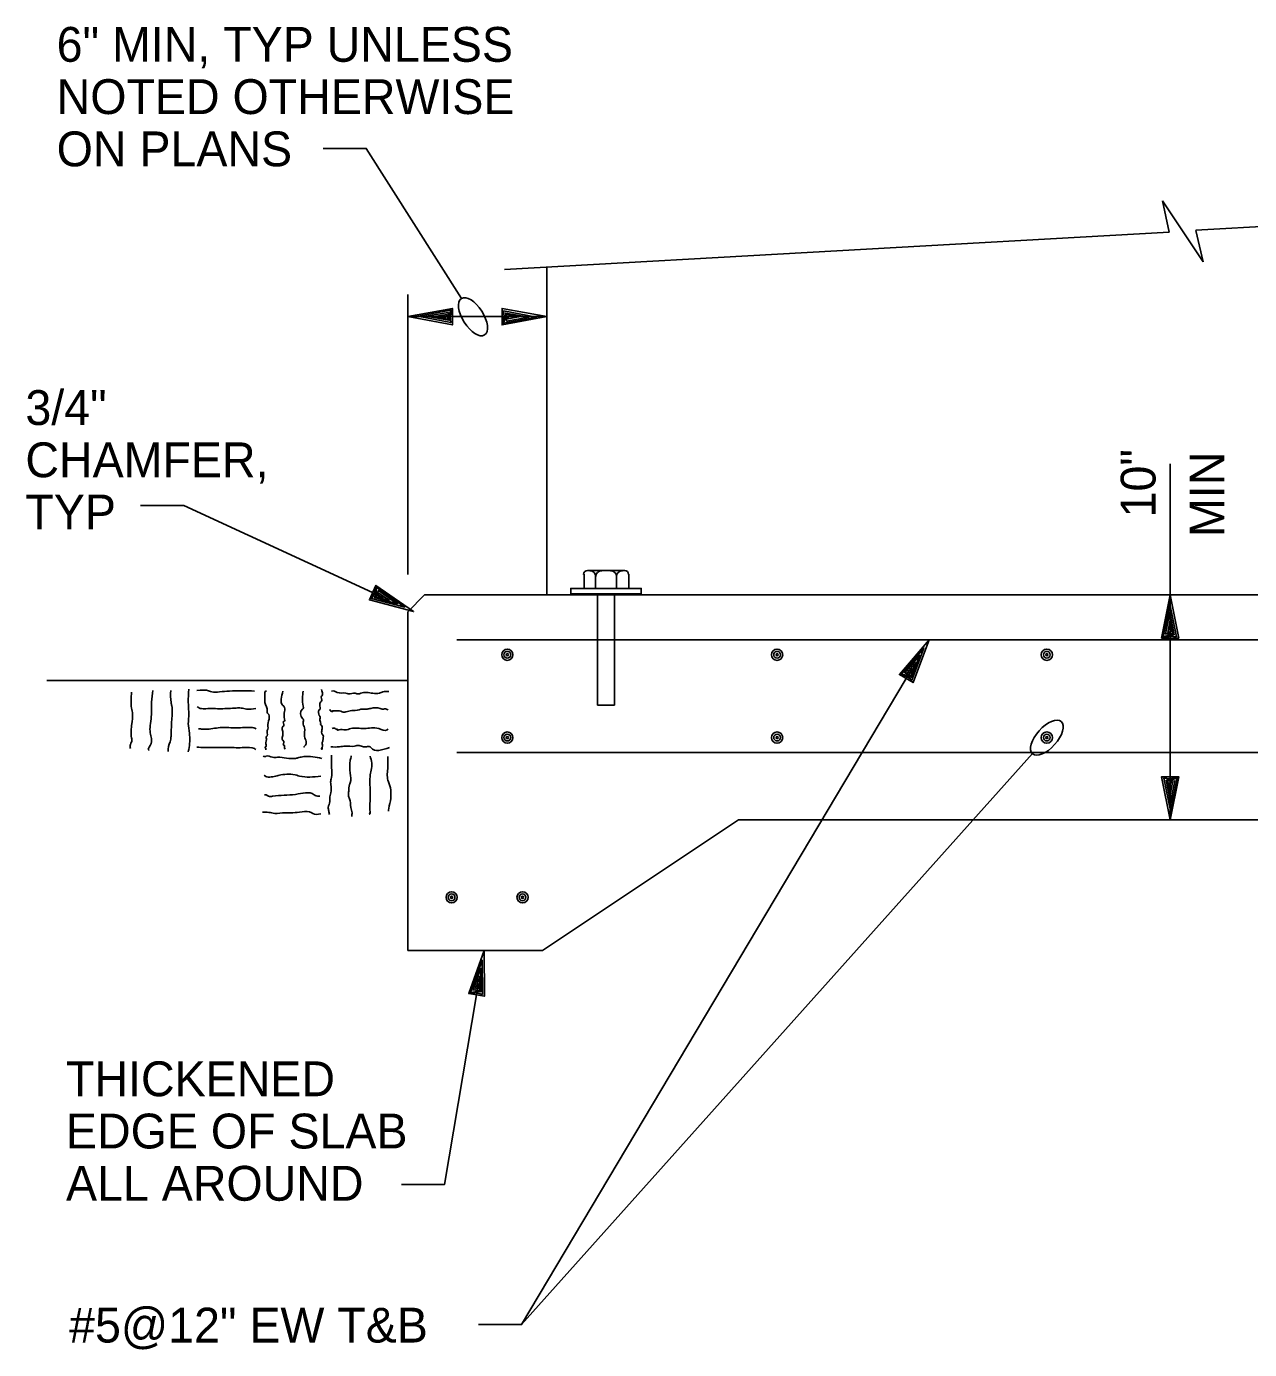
# Model space of a CAD drawing. Extents: x -121875 to -117742, y -103854 to -101122.
# Drawn here: x -121845.8 to -121635, y -102442.1 to -102214.2 of the extents above; entities that cross this region are included whole.
import ezdxf

# ---------------------------------------------------------------- set-up
doc = ezdxf.new("R2010")
doc.units = 0
for name, color, linetype in [('G-MARK', 7, 'Continuous'), ('G-TEXT', 7, 'Continuous'), ('Misc CnstDet(22)', 7, 'Continuous')]:
    doc.layers.add(name, color=color, linetype=linetype)

msp = doc.modelspace()

# ---------------------------------------------------------------- linework, layer by layer
at = {"layer": 'G-MARK'}
for p, q in [((-121756.12, -102255.67), (-121756.12, -102312.1)), ((-121780.06, -102308.56), (-121780.06, -102260.32)), ((-121780.06, -102264.16), (-121756.12, -102264.16)), ((-121648.67, -102289.5), (-121648.67, -102312.1)), ((-121648.67, -102312.1), (-121648.67, -102350.84))]:
    msp.add_line(p, q, dxfattribs=at)
for points in [[(-121794.66, -102235.19), (-121787.21, -102235.19), (-121770.8, -102261.05)], [(-121826.11, -102296.67), (-121818.67, -102296.67), (-121786.12, -102311.7)], [(-121767.88, -102437.78), (-121760.44, -102437.78), (-121694.16, -102326.51)], [(-121767.88, -102437.78), (-121760.44, -102437.78), (-121672.39, -102339.42)], [(-121781.17, -102413.63), (-121773.73, -102413.63), (-121768.21, -102380.99)]]:
    msp.add_lwpolyline(points, dxfattribs=at)
at = {"layer": 'G-TEXT'}
for points in [[(-121772.37, -102262.74), (-121772.37, -102265.59), (-121780.06, -102264.16), (-121772.37, -102262.74), (-121772.74, -102264.16), (-121772.62, -102265.16), (-121778.32, -102264.1), (-121772.62, -102263.05), (-121772.99, -102264.16), (-121772.99, -102264.78), (-121776.96, -102264.1), (-121773.12, -102263.42), (-121773.18, -102264.6), (-121775.53, -102264.16), (-121773.36, -102263.79), (-121773.55, -102264.35), (-121774.29, -102264.16), (-121772.37, -102264.16)], [(-121763.81, -102265.59), (-121763.81, -102262.74), (-121756.12, -102264.16), (-121763.81, -102265.59), (-121763.44, -102264.16), (-121763.56, -102263.17), (-121757.86, -102264.23), (-121763.56, -102265.28), (-121763.19, -102264.16), (-121763.19, -102263.54), (-121759.22, -102264.23), (-121763.07, -102264.91), (-121763.01, -102263.73), (-121760.65, -102264.16), (-121762.82, -102264.54), (-121762.63, -102263.98), (-121761.89, -102264.16), (-121763.81, -102264.16)], [(-121785.55, -102310.46), (-121786.69, -102312.94), (-121779.08, -102314.95), (-121785.55, -102310.46), (-121785.78, -102311.86), (-121786.31, -102312.71), (-121780.58, -102314.2), (-121785.43, -102310.79), (-121785.56, -102311.96), (-121785.81, -102312.53), (-121781.87, -102313.6), (-121785.13, -102311.34), (-121785.57, -102312.44), (-121783.19, -102313.06), (-121785.06, -102311.78), (-121785.13, -102312.37), (-121784.32, -102312.54), (-121786.12, -102311.71)], [(-121650.16, -102319.54), (-121647.19, -102319.54), (-121648.67, -102312.1), (-121650.16, -102319.54), (-121648.67, -102319.18), (-121647.59, -102319.3), (-121648.74, -102313.71), (-121649.89, -102319.3), (-121648.67, -102318.94), (-121648, -102318.94), (-121648.74, -102315.07), (-121649.49, -102318.82), (-121648.2, -102318.77), (-121648.67, -102316.44), (-121649.08, -102318.59), (-121648.47, -102318.41), (-121648.67, -102317.63), (-121648.67, -102319.54)], [(-121695.33, -102325.81), (-121692.98, -102327.2), (-121690.19, -102319.85), (-121695.33, -102325.81), (-121693.96, -102326.19), (-121693.18, -102326.8), (-121691.1, -102321.25), (-121694.99, -102325.72), (-121693.84, -102325.97), (-121693.3, -102326.29), (-121691.83, -102322.48), (-121694.41, -102325.49), (-121693.37, -102326.04), (-121692.5, -102323.74), (-121693.97, -102325.46), (-121693.39, -102325.59), (-121693.14, -102324.8), (-121694.15, -102326.51)], [(-121647.19, -102343.4), (-121650.16, -102343.4), (-121648.67, -102350.84), (-121647.19, -102343.4), (-121648.67, -102343.76), (-121649.76, -102343.64), (-121648.61, -102349.23), (-121647.46, -102343.64), (-121648.67, -102344), (-121649.35, -102344), (-121648.61, -102347.86), (-121647.86, -102344.11), (-121649.15, -102344.17), (-121648.67, -102346.5), (-121648.27, -102344.35), (-121648.88, -102344.53), (-121648.67, -102345.31), (-121648.67, -102343.4)], [(-121769.55, -102380.76), (-121766.86, -102381.22), (-121766.91, -102373.35), (-121769.55, -102380.76), (-121768.14, -102380.62), (-121767.19, -102380.91), (-121767.25, -102374.99), (-121769.27, -102380.56), (-121768.1, -102380.38), (-121767.49, -102380.48), (-121767.49, -102376.39), (-121768.82, -102380.13), (-121767.64, -102380.27), (-121767.67, -102377.81), (-121768.41, -102379.95), (-121767.83, -102379.86), (-121767.88, -102379.03), (-121768.21, -102380.99)]]:
    msp.add_lwpolyline(points, dxfattribs=at)
for centre, major_axis in [((-121768.83, -102264.17), (1.99, -3.14)), ((-121669.92, -102336.68), (2.48, 2.77))]:
    msp.add_ellipse(centre, major_axis=major_axis, ratio=0.483333, dxfattribs=at)
at = {"layer": 'Misc CnstDet(22)'}
for p, q in [((-121644.26, -102249.28), (-121531.59, -102242.89)), ((-121648.85, -102249.59), (-121649.97, -102244.2)), ((-121642.96, -102254.74), (-121649.97, -102244.2)), ((-121763.38, -102256.04), (-121648.85, -102249.59)), ((-121648.85, -102249.59), (-121648.85, -102249.59)), ((-121642.96, -102254.74), (-121644.26, -102249.34)), ((-121644.26, -102249.34), (-121644.26, -102249.34)), ((-121756.12, -102264.16), (-121756.12, -102264.16)), ((-121749.68, -102310.98), (-121749.68, -102308.5)), ((-121749.06, -102307.88), (-121742.73, -102307.88)), ((-121747.69, -102310.98), (-121747.69, -102308.87)), ((-121744.1, -102310.98), (-121744.1, -102308.87)), ((-121741.99, -102310.98), (-121741.99, -102308.5)), ((-121780.06, -102315), (-121777.16, -102312.1)), ((-121777.16, -102312.1), (-121516.95, -102312.1)), ((-121747.35, -102311.91), (-121747.35, -102331.1)), ((-121744.44, -102311.91), (-121744.44, -102331.1)), ((-121641.32, -102312.1), (-121652.39, -102312.1)), ((-121780.06, -102315), (-121780.06, -102373.35)), ((-121771.63, -102319.85), (-121522.48, -102319.85)), ((-121780.06, -102326.86), (-121842.26, -102326.86)), ((-121747.35, -102331.1), (-121744.44, -102331.1)), ((-121771.63, -102339.22), (-121522.48, -102339.22)), ((-121756.82, -102373.35), (-121723.06, -102350.84)), ((-121723.06, -102350.84), (-121571.05, -102350.84)), ((-121642.71, -102350.84), (-121652.39, -102350.84)), ((-121780.06, -102373.35), (-121756.81, -102373.35))]:
    msp.add_line(p, q, dxfattribs=at)
msp.add_lwpolyline([(-121751.97, -102311.91), (-121739.82, -102311.91), (-121739.82, -102310.98), (-121751.97, -102310.98)], close=True, dxfattribs=at)
for centre, radius in [((-121762.91, -102322.39), 0.969), ((-121716.42, -102322.39), 0.969), ((-121669.93, -102322.39), 0.969), ((-121762.91, -102322.39), 0.581), ((-121762.91, -102322.39), 0.176), ((-121716.42, -102322.39), 0.581), ((-121716.42, -102322.39), 0.176), ((-121669.93, -102322.39), 0.581), ((-121669.93, -102322.39), 0.176), ((-121762.91, -102336.67), 0.969), ((-121762.91, -102336.67), 0.581), ((-121762.91, -102336.67), 0.176), ((-121716.42, -102336.67), 0.969), ((-121716.42, -102336.67), 0.581), ((-121716.42, -102336.67), 0.176), ((-121669.93, -102336.67), 0.969), ((-121669.93, -102336.67), 0.581), ((-121669.93, -102336.67), 0.176), ((-121772.51, -102364.18), 0.969), ((-121772.51, -102364.18), 0.581), ((-121772.51, -102364.18), 0.176), ((-121760.29, -102364.18), 0.969), ((-121760.29, -102364.18), 0.581), ((-121760.29, -102364.18), 0.176)]:
    msp.add_circle(centre, radius, dxfattribs=at)
for centre, radius, start, end in [((-121749.08, -102308.56), 0.674, 90, 180), ((-121748.68, -102308.93), 1.01, 360, 90), ((-121746.65, -102308.93), 1.01, 90, 180), ((-121745.1, -102308.93), 1.01, 360, 90), ((-121743.08, -102308.93), 1.01, 90, 180), ((-121742.68, -102308.56), 0.674, 0, 90)]:
    msp.add_arc(centre, radius, start, end, dxfattribs=at)
for points in [[(-121817.82, -102328.34), (-121817.89, -102330.64), (-121817.82, -102333.06), (-121817.89, -102334.23), (-121817.7, -102335.91), (-121817.64, -102337.33), (-121817.82, -102338.7), (-121817.89, -102339.13)], [(-121827.68, -102328.84), (-121827.68, -102331.57), (-121827.5, -102332.62), (-121827.62, -102334.3), (-121827.68, -102336.71), (-121827.68, -102337.46), (-121827.87, -102337.83), (-121827.87, -102338.57)], [(-121824.02, -102328.53), (-121824.21, -102330.58), (-121824.27, -102333.06), (-121824.46, -102334.61), (-121824.46, -102335.85), (-121824.46, -102338.02), (-121824.71, -102338.82), (-121824.64, -102338.82)], [(-121820.92, -102328.53), (-121820.86, -102330.64), (-121820.74, -102331.2), (-121820.74, -102333.61), (-121820.86, -102336.28), (-121820.92, -102336.96), (-121821.36, -102338.64), (-121821.36, -102339.07)], [(-121806.48, -102328.65), (-121810.82, -102328.65), (-121812.49, -102328.78), (-121813.86, -102328.78), (-121814.23, -102328.65), (-121816.4, -102328.53)], [(-121804.43, -102328.65), (-121804.55, -102328.65), (-121804.68, -102329.4), (-121804.68, -102330.64), (-121804.31, -102332.13), (-121804.31, -102332.37), (-121804.18, -102332.5), (-121804.18, -102334.73), (-121804.18, -102335.23), (-121804.31, -102335.47), (-121804.31, -102336.34), (-121804.43, -102336.47), (-121804.43, -102337.02), (-121804.55, -102337.52), (-121804.55, -102338.26), (-121804.68, -102338.39), (-121804.55, -102338.51), (-121804.55, -102338.76)], [(-121801.58, -102328.65), (-121801.58, -102331.13), (-121801.45, -102331.26), (-121801.33, -102333.49), (-121801.33, -102333.86), (-121801.45, -102333.86), (-121801.45, -102334.61), (-121801.58, -102334.73), (-121801.58, -102335.97), (-121801.58, -102337.15), (-121801.45, -102337.27), (-121801.45, -102338.02), (-121801.33, -102338.02), (-121801.33, -102338.26), (-121801.2, -102338.64)], [(-121798.1, -102328.65), (-121798.1, -102331.26), (-121798.1, -102331.63), (-121798.23, -102331.75), (-121798.23, -102333.37), (-121798.1, -102333.49), (-121798.1, -102334.11), (-121797.86, -102334.98), (-121797.86, -102336.47), (-121797.86, -102338.14), (-121797.98, -102338.26), (-121797.86, -102338.26)], [(-121794.94, -102328.41), (-121794.82, -102328.78), (-121794.82, -102329.4), (-121794.94, -102329.52), (-121794.94, -102330.39), (-121795.07, -102330.51), (-121795.19, -102331.51), (-121795.19, -102331.75), (-121795.31, -102331.88), (-121795.31, -102332.87), (-121795.19, -102333.12), (-121795.19, -102333.86), (-121795.07, -102334.11), (-121795.07, -102334.48), (-121794.94, -102334.61), (-121794.82, -102336.09), (-121794.69, -102336.22), (-121794.69, -102337.15), (-121794.69, -102337.27), (-121794.82, -102337.52), (-121794.82, -102338.39), (-121794.94, -102338.64), (-121794.82, -102338.64), (-121794.82, -102338.51)], [(-121783.35, -102328.72), (-121784.34, -102328.78), (-121784.96, -102329.03), (-121786.08, -102329.03), (-121788.18, -102329.03), (-121788.56, -102329.15), (-121789.11, -102329.03), (-121790.35, -102329.15), (-121790.73, -102329.03), (-121792.21, -102328.9), (-121792.71, -102328.65), (-121793.21, -102328.65)], [(-121806.23, -102331.63), (-121807.84, -102331.75), (-121808.77, -102331.57), (-121809.64, -102331.57), (-121812.24, -102331.69), (-121814.85, -102331.69), (-121815.84, -102331.63), (-121816.34, -102331.38)], [(-121783.47, -102331.88), (-121783.72, -102331.75), (-121784.46, -102331.75), (-121784.84, -102331.63), (-121786.45, -102331.63), (-121787.07, -102331.75), (-121787.81, -102331.75), (-121789.11, -102332), (-121789.73, -102332), (-121790.73, -102332.25), (-121791.35, -102332.25), (-121791.59, -102332.13), (-121793.08, -102332.13), (-121792.96, -102332.13), (-121793.45, -102332), (-121793.45, -102331.88), (-121793.45, -102332)], [(-121806.17, -102335.16), (-121806.41, -102335.04), (-121807.28, -102334.92), (-121809.82, -102334.98), (-121812.74, -102334.98), (-121815.22, -102335.23), (-121815.96, -102335.16), (-121816.15, -102335.16)], [(-121783.47, -102335.23), (-121783.6, -102335.35), (-121785.08, -102335.1), (-121787.56, -102335.1), (-121789.86, -102335.1), (-121790.85, -102335.35), (-121791.97, -102335.35), (-121792.21, -102335.35), (-121792.21, -102335.23), (-121792.21, -102335.35), (-121792.21, -102335.23), (-121792.46, -102335.23), (-121792.59, -102335.1), (-121793.08, -102335.1)], [(-121806.23, -102338.7), (-121806.48, -102338.57), (-121808.27, -102338.39), (-121811, -102338.39), (-121813.79, -102338.39), (-121816.4, -102338.33)], [(-121794.88, -102340.25), (-121797.98, -102339.94), (-121798.85, -102340.12), (-121799.41, -102340.25), (-121802.51, -102340.06), (-121803.38, -102340.06), (-121804.49, -102339.88), (-121804.62, -102339.94), (-121804.99, -102339.88)], [(-121793.21, -102339.69), (-121793.21, -102341.86), (-121793.21, -102343.53), (-121793.33, -102343.97), (-121793.33, -102344.77), (-121793.33, -102346.2), (-121793.52, -102347.13), (-121793.52, -102347.69), (-121793.76, -102348.68), (-121793.7, -102349.3), (-121793.58, -102349.92)], [(-121783.22, -102338.39), (-121786.45, -102338.39), (-121786.57, -102338.26), (-121787.19, -102338.26), (-121787.69, -102338.26), (-121788.43, -102338.02), (-121789.24, -102338.14), (-121790.85, -102338.14), (-121791.84, -102338.26), (-121793.33, -102338.26)], [(-121789.8, -102339.81), (-121789.98, -102340.56), (-121789.98, -102342.79), (-121789.98, -102344.46), (-121790.11, -102344.77), (-121790.23, -102345.89), (-121790.29, -102346.64), (-121790.11, -102347.19), (-121789.86, -102348.68), (-121789.67, -102349.61), (-121789.73, -102350.23)], [(-121786.57, -102339.88), (-121786.26, -102341.05), (-121786.39, -102342.29), (-121786.57, -102343.35), (-121786.57, -102345.27), (-121786.57, -102347.57), (-121786.57, -102349.49), (-121786.57, -102349.74), (-121786.63, -102349.86), (-121786.63, -102349.61)], [(-121783.53, -102339.94), (-121783.53, -102342.05), (-121783.6, -102343.22), (-121783.41, -102344.28), (-121782.98, -102345.7), (-121782.98, -102346.39), (-121782.98, -102347.13), (-121783.35, -102348.87), (-121783.41, -102349.36)], [(-121795.07, -102343.29), (-121798.72, -102343.29), (-121799.16, -102343.16), (-121801.95, -102343.1), (-121802.82, -102343.29), (-121804.74, -102343.22), (-121804.8, -102343.16)], [(-121795.25, -102346.76), (-121796, -102346.64), (-121796.18, -102346.51), (-121799.41, -102346.45), (-121803.38, -102346.76), (-121804.06, -102346.76), (-121804.49, -102346.51), (-121804.74, -102346.51)], [(-121795.07, -102349.8), (-121796.43, -102349.74), (-121796.62, -102349.61), (-121798.29, -102349.43), (-121799.9, -102349.61), (-121801.2, -102349.61), (-121803, -102349.74), (-121804, -102349.55), (-121805.11, -102349.49)]]:
    msp.add_spline(points, degree=3, dxfattribs=at)

# ---------------------------------------------------------------- texts
at = {"layer": 'G-MARK'}
for s, p in [('6" MIN, TYP UNLESS', (-121840.58, -102220.26)), ('NOTED OTHERWISE', (-121840.58, -102229.26)), ('ON PLANS', (-121840.58, -102238.26)), ('3/4"', (-121845.97, -102282.82)), ('CHAMFER,', (-121845.97, -102291.82)), ('TYP', (-121845.97, -102300.82))]:
    msp.add_text(s, height=6, dxfattribs=at).set_placement(p)
at = {"layer": 'Misc CnstDet(22)'}
for s, p in [('10"', (-121651.19, -102298.74)), ('MIN', (-121639.33, -102302.12))]:
    msp.add_text(s, height=6, rotation=90, dxfattribs=at).set_placement(p)
for s, p in [('THICKENED', (-121838.97, -102398.44)), ('EDGE OF SLAB', (-121838.97, -102407.44)), ('ALL AROUND', (-121838.97, -102416.44)), ('#5@12" EW T&B', (-121838.43, -102440.87))]:
    msp.add_text(s, height=6, dxfattribs=at).set_placement(p)

doc.saveas('drawing.dxf')
